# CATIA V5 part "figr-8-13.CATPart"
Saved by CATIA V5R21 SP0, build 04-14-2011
Part number: Part1
Bounding box of the stored display mesh (mm): x 4.549 to 89.781, y -52.238 to 26.36, z 54 to 147.773
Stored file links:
  D:\CATIA V5R21 E-RESOURCES\CATIA-V5R21\catia-v5r21-prt\c08-catia-v5r20-prt\c08-catia-v5r21-figr-8-13.CATPart
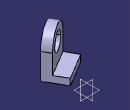
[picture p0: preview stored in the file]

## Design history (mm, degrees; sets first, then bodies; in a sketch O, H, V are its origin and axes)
Body1 (main body)
  Sketch1 on yz-plane, origin (0, 0, 0), H (0, 1, 0), V (0, 0, 1)
    point P1 (-104.4861, 0)
    line L1 (-104.4861, 0) -> (-104.4861, 44.267)
    arc A1 centre (-69.7903, 44.267) radius 34.6958 from (-104.4861, 44.267) to (-35.0946, 44.267) cw
    line L2 (-35.0946, 44.267) -> (-35.0946, 0)
    point P5 (-35.0946, 0)
    line L3 (-35.0946, 0) -> (-104.4861, 0)
    circle A2 centre (-69.7903, 44.267) radius 19.5413
    coincidence: P1 H, P5 H
    vertical: L1 V
    tangency: A1 L1, L2 A1
    horizontal: L3 H
  Pad1: profile Sketch1, direction (1, 0, 0), length 20
  Sketch2 on face of Pad1, origin (0, 0, 0), H (0, -1, 0), V (0, 0, 1)
    point P1 (35.0946, 0)
    line L1 (35.0946, 0) -> (104.4861, 0)
    line L2 (104.4861, 0) -> (104.4861, -15)
    line L3 (104.4861, -15) -> (35.0946, -15)
    line L4 (35.0946, -15) -> (35.0946, 0)
    reference projected line E1 (35.0946, 0) -> (35.0946, 44.267) from edge [face of Pad1 | face of Pad1]
    reference projected line E2 (104.4861, 44.267) -> (104.4861, 0) from edge [face of Pad1 | face of Pad1]
    distance L3 L1 = 15
    coincidence: P1 H, L4 E1, L2 E2
    horizontal: L1 H, L3 H
    vertical: L2 V, L4 V
  Pad2: profile Sketch2, direction (1, 0, 0), length 50
  Translate1: ToTransfor Pad2, Direction xy-plane, Length 69
  Rotate1: ToTransfor Translate1, Axis edge, Angle 121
